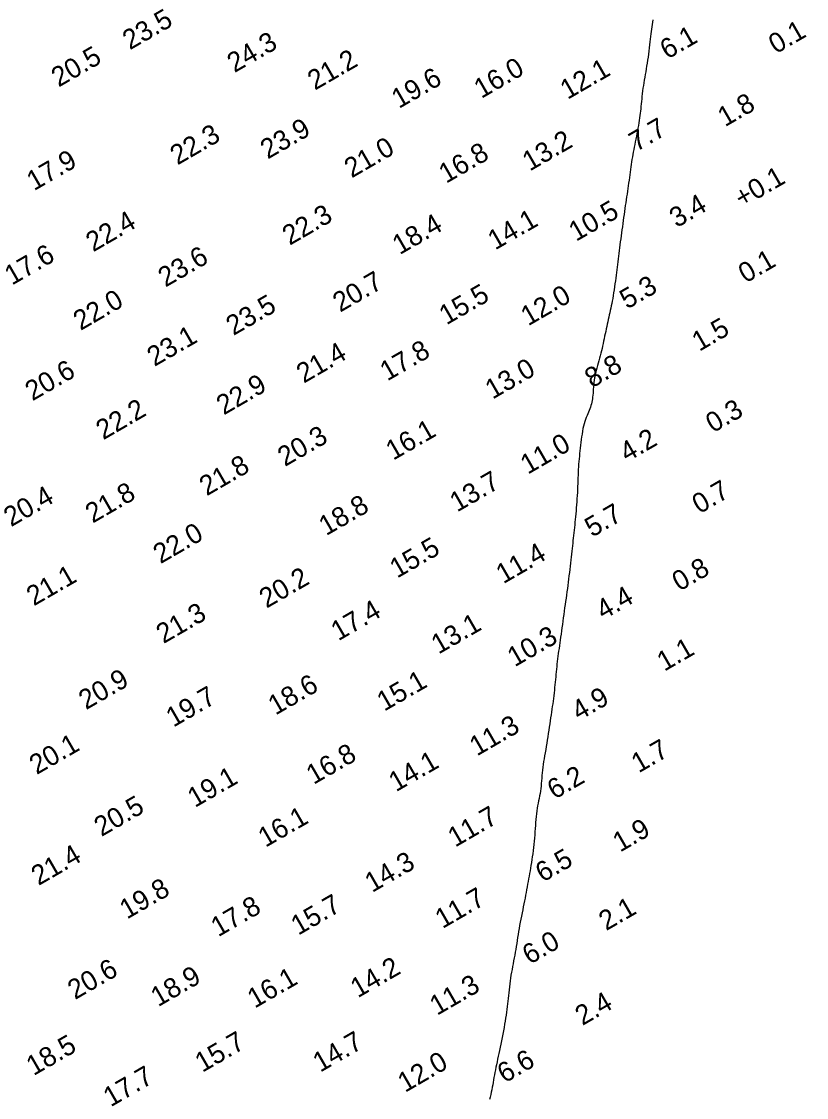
# Model space of a CAD drawing. Extents: x 3024098 to 3056816, y 418252 to 509144.
# Drawn here: x 3027005.2 to 3027204.4, y 423122.1 to 423395.3 of the extents above; entities that cross this region are included whole.
import ezdxf

# ---------------------------------------------------------------- set-up
doc = ezdxf.new("R2010")
doc.units = 0
doc.layers.add('V-CHAN-CONT-EL10', color=7, linetype='Continuous')
doc.layers.add('V-TOPO-SOUN-0911', color=7, linetype='Continuous')

msp = doc.modelspace()

# ---------------------------------------------------------------- linework, layer by layer
at = {"layer": 'V-CHAN-CONT-EL10'}
msp.add_lwpolyline([(3027165.42, 423395.74), (3027165.34, 423395.13), (3027165.25, 423394.54), (3027165.16, 423393.96), (3027165.07, 423393.38), (3027164.99, 423392.79), (3027164.9, 423392.17), (3027164.81, 423391.52), (3027164.73, 423390.84), (3027164.65, 423390.11), (3027164.57, 423389.36), (3027164.48, 423388.59), (3027164.39, 423387.8), (3027164.3, 423387.02), (3027164.21, 423386.23), (3027164.1, 423385.46), (3027163.99, 423384.71), (3027163.87, 423383.97), (3027163.75, 423383.25), (3027163.63, 423382.54), (3027163.5, 423381.84), (3027163.38, 423381.14), (3027163.26, 423380.44), (3027163.15, 423379.75), (3027163.04, 423379.05), (3027162.94, 423378.35), (3027162.85, 423377.66), (3027162.76, 423376.97), (3027162.68, 423376.29), (3027162.61, 423375.63), (3027162.54, 423374.98), (3027162.47, 423374.35), (3027162.41, 423373.73), (3027162.35, 423373.14), (3027162.29, 423372.56), (3027162.23, 423371.98), (3027162.16, 423371.4), (3027162.08, 423370.8), (3027162, 423370.2), (3027161.9, 423369.57), (3027161.79, 423368.92), (3027161.66, 423368.24), (3027161.53, 423367.55), (3027161.39, 423366.85), (3027161.25, 423366.15), (3027161.1, 423365.45), (3027160.96, 423364.76), (3027160.83, 423364.08), (3027160.7, 423363.42), (3027160.58, 423362.78), (3027160.46, 423362.15), (3027160.35, 423361.53), (3027160.25, 423360.91), (3027160.14, 423360.29), (3027160.05, 423359.66), (3027159.95, 423359.03), (3027159.86, 423358.38), (3027159.77, 423357.72), (3027159.68, 423357.05), (3027159.59, 423356.37), (3027159.49, 423355.69), (3027159.4, 423354.99), (3027159.3, 423354.29), (3027159.21, 423353.59), (3027159.1, 423352.89), (3027159, 423352.18), (3027158.89, 423351.47), (3027158.78, 423350.75), (3027158.67, 423350.03), (3027158.56, 423349.3), (3027158.44, 423348.56), (3027158.33, 423347.81), (3027158.23, 423347.06), (3027158.12, 423346.29), (3027158.01, 423345.52), (3027157.91, 423344.75), (3027157.8, 423343.97), (3027157.7, 423343.19), (3027157.6, 423342.42), (3027157.49, 423341.64), (3027157.39, 423340.87), (3027157.28, 423340.1), (3027157.18, 423339.35), (3027157.08, 423338.6), (3027156.98, 423337.85), (3027156.88, 423337.12), (3027156.79, 423336.4), (3027156.7, 423335.69), (3027156.61, 423335), (3027156.53, 423334.32), (3027156.45, 423333.64), (3027156.37, 423332.96), (3027156.28, 423332.28), (3027156.2, 423331.59), (3027156.11, 423330.89), (3027156.02, 423330.17), (3027155.93, 423329.44), (3027155.82, 423328.69), (3027155.72, 423327.93), (3027155.6, 423327.18), (3027155.49, 423326.43), (3027155.37, 423325.71), (3027155.25, 423325), (3027155.13, 423324.33), (3027155, 423323.68), (3027154.88, 423323.08), (3027154.75, 423322.49), (3027154.63, 423321.92), (3027154.5, 423321.36), (3027154.37, 423320.81), (3027154.24, 423320.25), (3027154.11, 423319.68), (3027153.98, 423319.09), (3027153.85, 423318.49), (3027153.73, 423317.88), (3027153.6, 423317.26), (3027153.47, 423316.63), (3027153.34, 423316), (3027153.21, 423315.37), (3027153.08, 423314.74), (3027152.95, 423314.12), (3027152.82, 423313.51), (3027152.69, 423312.89), (3027152.55, 423312.28), (3027152.41, 423311.67), (3027152.26, 423311.06), (3027152.1, 423310.44), (3027151.94, 423309.82), (3027151.77, 423309.19), (3027151.59, 423308.56), (3027151.42, 423307.93), (3027151.24, 423307.3), (3027151.07, 423306.67), (3027150.92, 423306.04), (3027150.78, 423305.42), (3027150.65, 423304.81), (3027150.56, 423304.21), (3027150.48, 423303.63), (3027150.42, 423303.05), (3027150.36, 423302.49), (3027150.32, 423301.95), (3027150.28, 423301.42), (3027150.25, 423300.91), (3027150.2, 423300.42), (3027150.15, 423299.95), (3027150.1, 423299.5), (3027150.03, 423299.07), (3027149.95, 423298.64), (3027149.85, 423298.22), (3027149.74, 423297.81), (3027149.62, 423297.4), (3027149.47, 423296.99), (3027149.31, 423296.58), (3027149.13, 423296.15), (3027148.94, 423295.72), (3027148.74, 423295.27), (3027148.54, 423294.79), (3027148.35, 423294.29), (3027148.17, 423293.76), (3027148, 423293.18), (3027147.84, 423292.58), (3027147.71, 423291.93), (3027147.58, 423291.26), (3027147.48, 423290.57), (3027147.37, 423289.86), (3027147.28, 423289.14), (3027147.19, 423288.42), (3027147.11, 423287.71), (3027147.02, 423287.01), (3027146.94, 423286.32), (3027146.86, 423285.63), (3027146.79, 423284.95), (3027146.72, 423284.27), (3027146.65, 423283.6), (3027146.6, 423282.92), (3027146.55, 423282.23), (3027146.51, 423281.54), (3027146.48, 423280.85), (3027146.45, 423280.14), (3027146.43, 423279.43), (3027146.4, 423278.7), (3027146.38, 423277.97), (3027146.35, 423277.23), (3027146.32, 423276.47), (3027146.28, 423275.7), (3027146.23, 423274.92), (3027146.18, 423274.14), (3027146.13, 423273.36), (3027146.07, 423272.58), (3027146, 423271.81), (3027145.94, 423271.05), (3027145.87, 423270.31), (3027145.81, 423269.58), (3027145.74, 423268.87), (3027145.68, 423268.17), (3027145.61, 423267.48), (3027145.54, 423266.81), (3027145.47, 423266.14), (3027145.4, 423265.48), (3027145.32, 423264.82), (3027145.25, 423264.17), (3027145.17, 423263.51), (3027145.09, 423262.84), (3027145.01, 423262.17), (3027144.93, 423261.49), (3027144.85, 423260.79), (3027144.77, 423260.08), (3027144.68, 423259.34), (3027144.6, 423258.59), (3027144.51, 423257.81), (3027144.43, 423257.02), (3027144.34, 423256.21), (3027144.25, 423255.4), (3027144.15, 423254.58), (3027144.05, 423253.76), (3027143.95, 423252.94), (3027143.85, 423252.13), (3027143.74, 423251.32), (3027143.63, 423250.51), (3027143.51, 423249.7), (3027143.4, 423248.89), (3027143.28, 423248.07), (3027143.16, 423247.25), (3027143.05, 423246.42), (3027142.93, 423245.58), (3027142.82, 423244.73), (3027142.7, 423243.88), (3027142.59, 423243.04), (3027142.48, 423242.2), (3027142.36, 423241.38), (3027142.25, 423240.57), (3027142.14, 423239.78), (3027142.03, 423239.01), (3027141.93, 423238.27), (3027141.82, 423237.55), (3027141.72, 423236.85), (3027141.62, 423236.16), (3027141.52, 423235.48), (3027141.43, 423234.81), (3027141.34, 423234.15), (3027141.26, 423233.49), (3027141.18, 423232.84), (3027141.11, 423232.18), (3027141.04, 423231.53), (3027140.97, 423230.88), (3027140.91, 423230.22), (3027140.84, 423229.56), (3027140.78, 423228.9), (3027140.71, 423228.23), (3027140.65, 423227.56), (3027140.58, 423226.88), (3027140.51, 423226.2), (3027140.44, 423225.51), (3027140.36, 423224.83), (3027140.28, 423224.14), (3027140.19, 423223.46), (3027140.11, 423222.77), (3027140.02, 423222.08), (3027139.92, 423221.39), (3027139.82, 423220.69), (3027139.72, 423219.98), (3027139.61, 423219.26), (3027139.5, 423218.52), (3027139.39, 423217.75), (3027139.27, 423216.97), (3027139.15, 423216.17), (3027139.03, 423215.36), (3027138.9, 423214.53), (3027138.77, 423213.71), (3027138.64, 423212.88), (3027138.51, 423212.06), (3027138.38, 423211.25), (3027138.24, 423210.46), (3027138.1, 423209.67), (3027137.96, 423208.91), (3027137.83, 423208.15), (3027137.71, 423207.41), (3027137.6, 423206.68), (3027137.5, 423205.96), (3027137.41, 423205.25), (3027137.34, 423204.55), (3027137.28, 423203.86), (3027137.23, 423203.18), (3027137.18, 423202.51), (3027137.13, 423201.85), (3027137.08, 423201.2), (3027137.01, 423200.56), (3027136.93, 423199.93), (3027136.83, 423199.31), (3027136.71, 423198.7), (3027136.58, 423198.08), (3027136.45, 423197.47), (3027136.32, 423196.84), (3027136.19, 423196.21), (3027136.07, 423195.55), (3027135.96, 423194.88), (3027135.87, 423194.18), (3027135.8, 423193.46), (3027135.73, 423192.71), (3027135.68, 423191.95), (3027135.62, 423191.18), (3027135.57, 423190.4), (3027135.52, 423189.6), (3027135.46, 423188.8), (3027135.39, 423188), (3027135.31, 423187.2), (3027135.23, 423186.4), (3027135.14, 423185.6), (3027135.04, 423184.81), (3027134.94, 423184.03), (3027134.83, 423183.27), (3027134.72, 423182.52), (3027134.61, 423181.79), (3027134.49, 423181.07), (3027134.38, 423180.36), (3027134.26, 423179.67), (3027134.14, 423178.99), (3027134.02, 423178.3), (3027133.9, 423177.63), (3027133.78, 423176.95), (3027133.65, 423176.27), (3027133.53, 423175.58), (3027133.4, 423174.89), (3027133.27, 423174.19), (3027133.14, 423173.48), (3027133, 423172.77), (3027132.86, 423172.04), (3027132.71, 423171.29), (3027132.56, 423170.54), (3027132.4, 423169.77), (3027132.24, 423168.99), (3027132.08, 423168.2), (3027131.93, 423167.41), (3027131.77, 423166.62), (3027131.63, 423165.83), (3027131.49, 423165.05), (3027131.35, 423164.27), (3027131.23, 423163.5), (3027131.11, 423162.74), (3027130.99, 423161.98), (3027130.88, 423161.23), (3027130.76, 423160.48), (3027130.64, 423159.75), (3027130.52, 423159.01), (3027130.38, 423158.28), (3027130.25, 423157.56), (3027130.1, 423156.83), (3027129.96, 423156.11), (3027129.82, 423155.39), (3027129.69, 423154.66), (3027129.56, 423153.93), (3027129.43, 423153.2), (3027129.32, 423152.46), (3027129.21, 423151.72), (3027129.12, 423150.97), (3027129.02, 423150.23), (3027128.94, 423149.49), (3027128.85, 423148.75), (3027128.77, 423148.02), (3027128.69, 423147.31), (3027128.61, 423146.6), (3027128.53, 423145.9), (3027128.45, 423145.2), (3027128.36, 423144.5), (3027128.27, 423143.79), (3027128.17, 423143.06), (3027128.06, 423142.31), (3027127.94, 423141.54), (3027127.81, 423140.74), (3027127.67, 423139.92), (3027127.52, 423139.08), (3027127.37, 423138.23), (3027127.21, 423137.38), (3027127.04, 423136.54), (3027126.88, 423135.7), (3027126.71, 423134.89), (3027126.54, 423134.1), (3027126.37, 423133.33), (3027126.2, 423132.59), (3027126.04, 423131.86), (3027125.89, 423131.16), (3027125.74, 423130.47), (3027125.59, 423129.8), (3027125.46, 423129.14), (3027125.34, 423128.49), (3027125.23, 423127.85), (3027125.12, 423127.22), (3027125.01, 423126.59), (3027124.91, 423125.97), (3027124.8, 423125.35), (3027124.69, 423124.74), (3027124.56, 423124.12), (3027124.43, 423123.5), (3027124.29, 423122.88), (3027124.14, 423122.24), (3027123.98, 423121.6)], dxfattribs=at)

# ---------------------------------------------------------------- texts
at = {"layer": 'V-TOPO-SOUN-0911'}
for s, p in [('23.5 ', (3027032.7, 423387.96)), ('0.1', (3027196.67, 423386.96)), ('24.3 ', (3027059.25, 423382.18)), ('6.1', (3027169.11, 423385.58)), ('20.5 ', (3027014.62, 423378.51)), ('21.2 ', (3027079.66, 423377.72)), ('16.0 ', (3027121.9, 423375.62)), ('12.1 ', (3027143.78, 423375.37)), ('19.6 ', (3027100.98, 423373.07)), ('1.8', (3027183.76, 423368.44)), ('23.9 ', (3027067.68, 423360.23)), ('7.7', (3027161.25, 423362.14)), ('22.3 ', (3027044.78, 423358.73)), ('21.0 ', (3027088.99, 423355.44)), ('13.2 ', (3027134.19, 423357.18)), ('17.9 ', (3027008.37, 423352.2)), ('16.8 ', (3027112.96, 423354.07)), ('+0.1 ', (3027188.01, 423347.88)), ('3.4', (3027171.49, 423342.82)), ('22.3 ', (3027073.26, 423338.35)), ('10.5 ', (3027145.95, 423339.34)), ('22.4 ', (3027023.39, 423336.68)), ('18.4 ', (3027101.18, 423335.96)), ('14.1 ', (3027125.41, 423337.15)), ('17.6 ', (3027002.75, 423328.22)), ('23.6 ', (3027041.73, 423327.73)), ('0.1', (3027188.99, 423328.76)), ('20.7 ', (3027086.06, 423321.36)), ('5.3', (3027158.89, 423322.15)), ('22.0 ', (3027020.19, 423316.73)), ('15.5 ', (3027113.05, 423318.14)), ('12.0 ', (3027133.78, 423317.88)), ('23.5 ', (3027058.98, 423315.45)), ('1.5', (3027177.22, 423311.42)), ('23.1 ', (3027038.93, 423307.59)), ('21.4 ', (3027076.84, 423303.34)), ('17.8 ', (3027098.03, 423303.9)), ('8.8', (3027150, 423302.14)), ('20.6 ', (3027007.97, 423298.86)), ('13.0 ', (3027124.75, 423299.28)), ('22.9 ', (3027056.53, 423295.27)), ('22.2 ', (3027025.95, 423288.97)), ('0.3', (3027180.71, 423290.75)), ('16.1 ', (3027099.52, 423283.77)), ('20.3 ', (3027072.05, 423282.18)), ('4.2', (3027158.89, 423283.34)), ('11.0 ', (3027133.68, 423280.21)), ('21.8 ', (3027052.2, 423274.74)), ('13.7 ', (3027115.75, 423270.63)), ('21.8 ', (3027023.26, 423267.81)), ('0.7', (3027177.26, 423270.18)), ('20.4 ', (3027002.53, 423266.89)), ('18.8 ', (3027082.51, 423264.63)), ('5.7', (3027150.03, 423264.24)), ('22.0 ', (3027040.47, 423257.51)), ('15.5 ', (3027100.52, 423253.84)), ('11.4 ', (3027127.49, 423252.43)), ('0.8', (3027172.18, 423250.53)), ('21.1 ', (3027008.32, 423246.8)), ('20.2 ', (3027067.39, 423246.23)), ('4.4', (3027152.89, 423243.31)), ('21.3 ', (3027041.24, 423237.24)), ('17.4 ', (3027085.6, 423237.93)), ('13.1 ', (3027111.04, 423234.56)), ('10.3 ', (3027130.38, 423231.33)), ('1.1', (3027168.35, 423230.2)), ('20.9 ', (3027021.56, 423220.44)), ('18.6 ', (3027069.65, 423219.07)), ('15.1 ', (3027097.26, 423220.06)), ('19.7 ', (3027043.73, 423216.01)), ('4.9', (3027146.69, 423217.69)), ('11.3 ', (3027120.77, 423208.69)), ('20.1 ', (3027009.04, 423203.98)), ('1.7', (3027161.84, 423204.4)), ('16.8 ', (3027079.33, 423201.47)), ('14.1 ', (3027100.25, 423199.62)), ('19.1 ', (3027049.2, 423195.62)), ('6.2', (3027140.49, 423197.71)), ('20.5 ', (3027025.48, 423188.25)), ('16.1 ', (3027067.11, 423185.51)), ('11.7 ', (3027115.26, 423185.56)), ('1.9', (3027157.12, 423184.29)), ('21.4 ', (3027009.52, 423175.82)), ('6.5', (3027137.49, 423176.65)), ('14.3 ', (3027094.19, 423174.05)), ('19.8 ', (3027031.96, 423167.29)), ('15.7 ', (3027075.43, 423163.19)), ('11.7 ', (3027112.04, 423164.89)), ('17.8 ', (3027055.12, 423162.79)), ('2.1', (3027153.59, 423164.36)), ('6.0', (3027134.17, 423155.78)), ('20.6 ', (3027018.77, 423146.85)), ('14.2 ', (3027090.55, 423147.31)), ('18.9 ', (3027039.86, 423145.04)), ('16.1 ', (3027064.39, 423144.67)), ('11.3 ', (3027110.66, 423142.85)), ('2.4', (3027147.57, 423140.29)), ('18.5 ', (3027008.26, 423127.56)), ('15.7 ', (3027051.08, 423128.38)), ('14.7 ', (3027081, 423128.41)), ('12.0 ', (3027102.54, 423123.29)), ('6.6', (3027127.82, 423125.67)), ('17.7 ', (3027027.82, 423119.62))]:
    msp.add_text(s, height=5, rotation=30, dxfattribs=at).set_placement(p)

doc.saveas('drawing.dxf')
